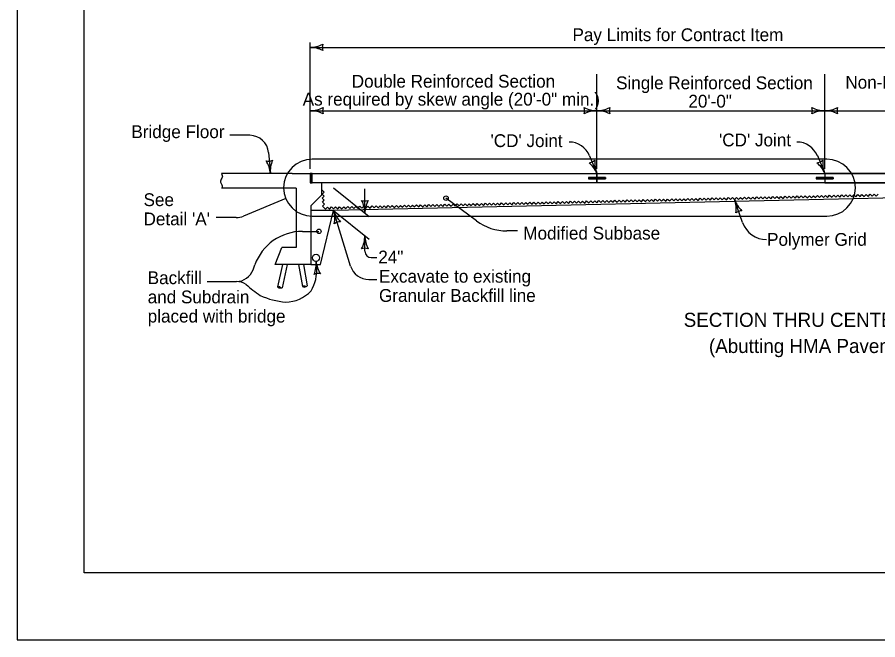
# Model space of a CAD drawing. Extents: x 10130 to 81668, y 5440 to 21644.
# Drawn here: x 13699 to 15045, y 5440 to 6413 of the extents above; entities that cross this region are included whole.
import ezdxf

# ---------------------------------------------------------------- set-up
doc = ezdxf.new("R2010")
doc.units = 0
for name, color, linetype in [('Cell', 7, 'Continuous'), ('dsnShtPlotShapeBatchPrint', 7, 'Continuous'), ('dsnStdBlockModified', 7, 'Continuous'), ('dsnStdBorder', 7, 'Continuous')]:
    doc.layers.add(name, color=color, linetype=linetype)

msp = doc.modelspace()

# ---------------------------------------------------------------- linework, layer by layer
at = {"layer": 'Cell'}
msp.add_lwpolyline([(13803.2, 7554.1), (16938.2, 7554.1), (16938.2, 5544.1), (13803.2, 5544.1)], close=True, dxfattribs=at)
at = {"layer": 'dsnShtPlotShapeBatchPrint'}
msp.add_lwpolyline([(13698.7, 5439.6), (17042.7, 5439.6), (17042.7, 8023.6), (13698.7, 8023.6)], close=True, dxfattribs=at)
at = {"layer": 'dsnStdBlockModified'}
for p, q in [((14160.1, 6153.9), (14160.1, 6168.7)), ((14160.1, 6168.7), (14605.6, 6168.7)), ((14160.1, 6153.9), (14160.1, 6168.7)), ((14605.6, 6168.7), (14605.6, 6162.2)), ((14605.6, 6162.2), (14605.6, 6168.7)), ((14605.6, 6162.2), (14605.6, 6168.7)), ((14605.6, 6168.7), (14962, 6168.7)), ((14962, 6168.7), (14962, 6162.2)), ((14175.4, 6153.9), (14160.1, 6153.9)), ((14197.2, 6153.9), (14175.4, 6153.9)), ((14605.6, 6153.9), (14197.2, 6153.9)), ((14605.6, 6162.2), (14592.2, 6162.2)), ((14592.2, 6162.2), (14592.2, 6160.4)), ((14592.2, 6162.2), (14592.2, 6160.4)), ((14618.9, 6162.2), (14592.2, 6162.2)), ((14592.2, 6162.2), (14605.6, 6162.2)), ((14592.2, 6160.4), (14605.6, 6160.4)), ((14618.9, 6162.2), (14605.6, 6162.2)), ((14605.6, 6160.4), (14605.6, 6153.9)), ((14605.6, 6153.9), (14605.6, 6160.4)), ((14605.6, 6160.3), (14618.9, 6160.4)), ((14962, 6153.9), (14605.6, 6153.9)), ((14618.9, 6160.4), (14618.9, 6162.2)), ((14948.6, 6162.2), (14948.6, 6160.4)), ((14962, 6162.2), (14948.6, 6162.2)), ((14948.6, 6162.2), (14948.6, 6160.4)), ((14948.6, 6160.4), (14962, 6160.4)), ((14975.3, 6162.2), (14962, 6162.2)), ((14962, 6160.4), (14962, 6153.9)), ((14144.9, 6078.1), (14170.7, 6078.1)), ((14067.6, 6018), (14070.3, 6025.6)), ((13995.8, 5999.6), (14041.5, 5999.6))]:
    msp.add_line(p, q, dxfattribs=at)
for centre, radius, start, end in [((14096.3, 6020), 71.3, 330.5092, 2.0511), ((14168, 6115.1), 163.6, 227.1442, 236.9942), ((14127.8, 6085.7), 118.5, 245.5915, 265.546), ((14118.3, 6022.6), 55, 270.3325, 316.7198)]:
    msp.add_arc(centre, radius, start, end, dxfattribs=at)
at = {"layer": 'dsnStdBorder'}
for p, q in [((14157.1, 6176.1), (14157.1, 6373.2)), ((14157.1, 6365.7), (15318.4, 6365.7)), ((14605.6, 6176.1), (14605.6, 6323.7)), ((14962, 6176.1), (14962, 6323.7)), ((14157.1, 6266.7), (14605.6, 6266.7)), ((14605.6, 6266.7), (14962, 6266.7)), ((14962, 6266.7), (15318.4, 6266.7)), ((14062.8, 6228.3), (14031.1, 6228.3)), ((14091.9, 6201.2), (14094.8, 6168.7)), ((14594, 6196.4), (14605.6, 6168.7)), ((14950.4, 6196.5), (14962, 6168.7)), ((14965.2, 6191), (14160.1, 6191)), ((14128.9, 6168.7), (14018.3, 6168.7)), ((14128.9, 6168.7), (14157.1, 6168.7)), ((14157.1, 6168.7), (14157.1, 6153.9)), ((14160.1, 6168.7), (14157.1, 6168.7)), ((14157.1, 6165.3), (14160.1, 6168.3)), ((14157.1, 6167.4), (14158, 6168.3)), ((14160.1, 6168.3), (14157.1, 6168.3)), ((14157.1, 6163.2), (14160.1, 6166.2)), ((14160.1, 6168.7), (15318.4, 6168.7)), ((14605.6, 6153.9), (14605.6, 6168.7)), ((15318.4, 6168.7), (14962, 6168.7)), ((14962, 6168.7), (14962, 6162.2)), ((14962, 6168.7), (14962, 6153.9)), ((14157.1, 6161.1), (14160.1, 6164.1)), ((14157.1, 6159), (14160.1, 6162)), ((14157.1, 6156.9), (14160.1, 6159.9)), ((14157.1, 6154.8), (14160.1, 6157.8)), ((14157.1, 6153.9), (14160.1, 6153.9)), ((14158.3, 6153.9), (14160.1, 6155.7)), ((15318.4, 6153.9), (14160.1, 6153.9)), ((14174.9, 6153.9), (14174.9, 6134.6)), ((14592.2, 6162.2), (14618.9, 6162.2)), ((14592.2, 6160.4), (14618.9, 6160.4)), ((14592.2, 6160.4), (14618.9, 6160.4)), ((14618.9, 6162.2), (14618.9, 6160.4)), ((14948.6, 6162.2), (14975.3, 6162.2)), ((14948.6, 6160.4), (14975.3, 6160.4)), ((14962, 6162.2), (14975.3, 6162.2)), ((14975.3, 6160.4), (14962, 6160.4)), ((14962, 6160.4), (14962, 6153.9)), ((14962, 6153.9), (15318.4, 6153.9)), ((14975.3, 6162.2), (14975.3, 6160.4)), ((14975.3, 6162.2), (14975.3, 6160.4)), ((14134.8, 6145.8), (14018.3, 6145.8)), ((14134.8, 6145.8), (14134.8, 6052.9)), ((14193.7, 6146.1), (14249, 6101.1)), ((14242.5, 6106.3), (14242.5, 6144.5)), ((14118.9, 6129.4), (14052.7, 6102.1)), ((14174.9, 6134.6), (14158.1, 6117.8)), ((15318.4, 6136.2), (14193.7, 6110.8)), ((14417.3, 6094.4), (14369.4, 6130)), ((14833.5, 6091.8), (14821, 6127.7)), ((14158.1, 6117.8), (14158.1, 6026.1)), ((14041.4, 6099.8), (14009.8, 6099.8)), ((14193.7, 6110.8), (14158.1, 6110.8)), ((14160.1, 6101.9), (14965.2, 6101.9)), ((14173, 6026.1), (14193.7, 6110.8)), ((14193.7, 6110.8), (14249, 6065.8)), ((14220.2, 6023.9), (14193.7, 6110.8)), ((14481.4, 6078.8), (14464.5, 6078.8)), ((14242.5, 6047), (14242.5, 6071)), ((14102.2, 6026.1), (14112.4, 6052.9)), ((14134.8, 6052.9), (14112.4, 6052.9)), ((14252.5, 6037), (14261.1, 6037)), ((14158.1, 6026.1), (14102.2, 6026.1)), ((14113.6, 6026.1), (14106.1, 5991.3)), ((14121.2, 6026.1), (14113.4, 5989.8)), ((14138.9, 6026.1), (14145.2, 5991.8)), ((14146.4, 6026.1), (14152.5, 5993.2)), ((14158.1, 6026.1), (14173, 6026.1)), ((14248.6, 6002.9), (14261.1, 6002.9))]:
    msp.add_line(p, q, dxfattribs=at)
for points in [[(14177.9, 6115.7), (14176.2, 6117.4), (14179.3, 6120.6), (14176, 6123.7), (14179.1, 6127), (14175.9, 6130.1), (14179, 6133.3), (14175.7, 6136.4), (14178.8, 6139.6), (14175.6, 6142.7), (14175.7, 6142.9)], [(14540.4, 6122.9), (14542, 6121.4), (14545.1, 6124.6), (14548.4, 6121.5), (14551.5, 6124.8), (14554.7, 6121.7), (14557.8, 6124.9), (14561, 6121.8), (14564.1, 6125.1), (14567.4, 6122), (14570.5, 6125.2), (14573.7, 6122.1), (14576.8, 6125.4), (14580, 6122.3), (14583.1, 6125.5), (14586.4, 6122.4), (14589.5, 6125.6), (14592.7, 6122.6), (14595.8, 6125.8), (14599, 6122.7), (14602.1, 6125.9), (14605.4, 6122.9), (14608.5, 6126.1), (14611.7, 6123), (14614.8, 6126.2), (14616.4, 6124.7)], [(14616.4, 6124.7), (14618, 6123.2), (14621.1, 6126.4), (14624.4, 6123.3), (14627.5, 6126.6), (14630.7, 6123.5), (14633.8, 6126.7), (14637, 6123.6), (14640.1, 6126.9), (14643.4, 6123.8), (14646.5, 6127), (14649.7, 6123.9), (14652.8, 6127.2), (14656.1, 6124.1), (14659.1, 6127.3), (14662.4, 6124.2), (14665.5, 6127.5), (14668.7, 6124.4), (14671.8, 6127.6), (14675.1, 6124.5), (14678.1, 6127.8), (14681.4, 6124.7), (14684.5, 6127.9), (14687.7, 6124.8), (14690.8, 6128), (14692.4, 6126.5)], [(14692.4, 6126.5), (14694.1, 6125), (14697.2, 6128.2), (14700.4, 6125.1), (14703.5, 6128.4), (14706.7, 6125.3), (14709.8, 6128.5), (14713.1, 6125.4), (14716.1, 6128.7), (14719.4, 6125.6), (14722.5, 6128.8), (14725.7, 6125.7), (14728.8, 6128.9), (14732.1, 6125.9), (14735.2, 6129.1), (14738.4, 6126), (14741.5, 6129.2), (14744.7, 6126.2), (14747.8, 6129.4), (14751.1, 6126.3), (14754.2, 6129.5), (14757.4, 6126.5), (14760.5, 6129.7), (14763.7, 6126.6), (14766.8, 6129.8), (14768.4, 6128.3)], [(14768.5, 6128.3), (14770.1, 6126.7), (14773.2, 6130), (14776.4, 6126.9), (14779.5, 6130.1), (14782.7, 6127), (14785.8, 6130.3), (14789.1, 6127.2), (14792.2, 6130.4), (14795.4, 6127.3), (14798.5, 6130.6), (14801.7, 6127.5), (14804.8, 6130.7), (14808.1, 6127.6), (14811.2, 6130.9), (14814.4, 6127.8), (14817.5, 6131), (14820.7, 6127.9), (14823.8, 6131.1), (14827.1, 6128.1), (14830.2, 6131.3), (14833.4, 6128.2), (14836.5, 6131.4), (14839.7, 6128.4), (14842.8, 6131.6), (14844.5, 6130)], [(14844.5, 6130), (14846.1, 6128.5), (14849.2, 6131.7), (14852.4, 6128.6), (14855.5, 6131.9), (14858.7, 6128.8), (14861.8, 6132), (14865.1, 6128.9), (14868.2, 6132.2), (14871.4, 6129.1), (14874.5, 6132.3), (14877.7, 6129.2), (14880.8, 6132.5), (14884.1, 6129.4), (14887.2, 6132.6), (14890.4, 6129.5), (14893.5, 6132.8), (14896.8, 6129.7), (14899.8, 6132.9), (14903.1, 6129.8), (14906.2, 6133.1), (14909.4, 6130), (14912.5, 6133.2), (14915.8, 6130.1), (14918.9, 6133.4), (14920.5, 6131.8)], [(14920.5, 6131.8), (14922.1, 6130.3), (14925.2, 6133.5), (14928.4, 6130.4), (14931.5, 6133.6), (14934.8, 6130.6), (14937.9, 6133.8), (14941.1, 6130.7), (14944.2, 6133.9), (14947.4, 6130.8), (14950.5, 6134.1), (14953.8, 6131), (14956.9, 6134.2), (14960.1, 6131.1), (14963.2, 6134.4), (14966.4, 6131.3), (14969.5, 6134.5), (14972.8, 6131.4), (14975.9, 6134.7), (14979.1, 6131.6), (14982.2, 6134.8), (14985.4, 6131.7), (14988.5, 6135), (14991.8, 6131.9), (14994.9, 6135.1), (14996.5, 6133.6)], [(14996.5, 6133.6), (14998.1, 6132.1), (15001.2, 6135.3), (15004.4, 6132.2), (15007.5, 6135.4), (15010.8, 6132.3), (15013.9, 6135.6), (15017.1, 6132.5), (15020.2, 6135.7), (15023.4, 6132.6), (15026.5, 6135.9), (15029.8, 6132.8), (15032.9, 6136), (15036.1, 6132.9), (15039.2, 6136.2), (15042.4, 6133.1), (15045.5, 6136.3)], [(14177.7, 6115.9), (14177.7, 6115.9), (14181, 6112.8), (14184.1, 6116.1), (14187.3, 6113), (14190.4, 6116.2), (14193.7, 6113.1), (14196.7, 6116.4), (14200, 6113.3), (14203.1, 6116.5), (14206.3, 6113.4), (14209.4, 6116.7), (14212.7, 6113.6), (14215.7, 6116.8), (14219, 6113.7), (14222.1, 6117), (14225.3, 6113.9), (14228.4, 6117.1), (14231.7, 6114), (14234.8, 6117.3), (14236.4, 6115.7)], [(14236.4, 6115.8), (14238, 6114.3), (14241.1, 6117.5), (14244.3, 6114.4), (14247.4, 6117.6), (14250.7, 6114.5), (14253.8, 6117.8), (14257, 6114.7), (14260.1, 6117.9), (14263.3, 6114.8), (14266.4, 6118.1), (14269.7, 6115), (14272.8, 6118.2), (14276, 6115.1), (14279.1, 6118.4), (14282.3, 6115.3), (14285.4, 6118.5), (14288.7, 6115.4), (14291.8, 6118.7), (14295, 6115.6), (14298.1, 6118.8), (14301.3, 6115.7), (14304.4, 6119), (14307.7, 6115.9), (14310.8, 6119.1), (14312.4, 6117.6)], [(14312.4, 6117.6), (14314, 6116), (14317.1, 6119.3), (14320.3, 6116.2), (14323.4, 6119.4), (14326.7, 6116.3), (14329.8, 6119.6), (14333, 6116.5), (14336.1, 6119.7), (14339.3, 6116.6), (14342.4, 6119.9), (14345.7, 6116.8), (14348.8, 6120), (14352, 6116.9), (14355.1, 6120.2), (14358.3, 6117.1), (14361.4, 6120.3), (14364.7, 6117.2), (14367.8, 6120.5), (14371, 6117.4), (14374.1, 6120.6), (14377.3, 6117.5), (14380.4, 6120.8), (14383.7, 6117.7), (14386.8, 6120.9), (14388.4, 6119.4)], [(14388.4, 6119.4), (14390, 6117.8), (14393.1, 6121.1), (14396.3, 6118), (14399.4, 6121.2), (14402.7, 6118.1), (14405.8, 6121.4), (14409, 6118.3), (14412.1, 6121.5), (14415.4, 6118.4), (14418.4, 6121.7), (14421.7, 6118.6), (14424.8, 6121.8), (14428, 6118.7), (14431.1, 6122), (14434.4, 6118.9), (14437.4, 6122.1), (14440.7, 6119), (14443.8, 6122.3), (14447, 6119.2), (14450.1, 6122.4), (14453.4, 6119.3), (14456.4, 6122.6), (14459.7, 6119.5), (14462.8, 6122.7), (14464.4, 6121.2)], [(14464.4, 6121.2), (14466, 6119.6), (14469.1, 6122.9), (14472.4, 6119.8), (14475.4, 6123), (14478.7, 6119.9), (14481.8, 6123.1), (14485, 6120.1), (14488.1, 6123.3), (14491.4, 6120.2), (14494.5, 6123.4), (14497.7, 6120.4), (14500.8, 6123.6), (14504, 6120.5), (14507.1, 6123.7), (14510.4, 6120.6), (14513.5, 6123.9), (14516.7, 6120.8), (14519.8, 6124), (14523, 6120.9), (14526.1, 6124.2), (14529.4, 6121.1), (14532.5, 6124.3), (14535.7, 6121.2), (14538.8, 6124.5), (14540.4, 6122.9)]]:
    msp.add_lwpolyline(points, dxfattribs=at)
for centre, radius in [((14369.4, 6130), 3.47), ((14170.7, 6078.1), 3.47), ((14166.1, 6036.8), 5.57)]:
    msp.add_circle(centre, radius, dxfattribs=at)
for centre, radius, start, end in [((14156.5, 6408.5), 42.7, 270, 298.0725), ((14192.4, 6365.7), 16.5, 162.2666, 197.7334), ((14156.5, 6323), 42.7, 61.9275, 90), ((14157.1, 6309.5), 42.7, 270, 298.0725), ((14157.1, 6224), 42.7, 61.9275, 90), ((14193, 6266.7), 16.5, 162.2666, 197.7334), ((14569.7, 6266.7), 16.5, 342.2666, 17.7333), ((14605.6, 6309.5), 42.7, 241.9275, 270), ((14605.6, 6224), 42.7, 90, 118.0725), ((14605.6, 6309.5), 42.7, 270, 298.0725), ((14605.6, 6224), 42.7, 61.9275, 90), ((14641.4, 6266.7), 16.5, 162.2666, 197.7334), ((14926.1, 6266.7), 16.5, 342.2666, 17.7333), ((14962, 6309.5), 42.7, 241.9275, 270), ((14962, 6224), 42.7, 90, 118.0725), ((14962, 6309.5), 42.7, 270, 298.0725), ((14962, 6224), 42.7, 61.9275, 90), ((14997.8, 6266.7), 16.5, 162.2666, 197.7334), ((14062.3, 6198.6), 29.7, 4.9696, 89.1065), ((14562.1, 6183.1), 34.7, 22.5907, 90), ((14918.4, 6183.1), 34.7, 22.5907, 90), ((14091.7, 6204.4), 16.5, 257.2356, 292.7023), ((14052.2, 6165), 42.7, 4.969, 33.0415), ((14137.3, 6172.4), 42.7, 156.8965, 184.969), ((14160.1, 6146.4), 44.6, 90, 269.9998), ((14591.8, 6201.8), 16.5, 274.8595, 310.3262), ((14566.1, 6152.3), 42.7, 22.5928, 50.6653), ((14645, 6185.1), 42.7, 174.5203, 202.5928), ((14948.2, 6201.8), 16.5, 274.8572, 310.3239), ((14922.5, 6152.3), 42.7, 22.5905, 50.663), ((15001.4, 6185.1), 42.7, 174.5181, 202.5905), ((14965.2, 6146.4), 44.6, 270.0002, 90), ((14242.5, 6142.2), 16.5, 252.2666, 287.7333), ((14199.8, 6106.3), 42.7, 360, 28.0725), ((14285.3, 6106.3), 42.7, 151.9275, 180), ((14861.4, 6141.7), 42.7, 199.1779, 227.2504), ((14780.7, 6113.7), 42.7, 351.1054, 19.1779), ((14041.4, 6129.5), 29.7, 270, 292.4496), ((14234.6, 6123.3), 42.7, 196.9537, 225.0262), ((14152.8, 6098.3), 42.7, 348.8812, 16.9537), ((14234.6, 6123.3), 42.7, 196.9537, 225.0262), ((14152.8, 6098.3), 42.7, 348.8812, 16.9537), ((14832.8, 6093.8), 16.5, 91.4446, 126.9113), ((14204.2, 6076.5), 16.5, 89.2203, 124.687), ((14204.2, 6076.5), 16.5, 89.2203, 124.687), ((14464.5, 6158), 79.2, 233.4243, 270), ((14870.9, 6104.8), 39.6, 199.1769, 270), ((14144.9, 5998.9), 79.2, 90, 160.3012), ((14199.8, 6071), 42.7, 331.9275, 360), ((14285.3, 6071), 42.7, 180, 208.0725), ((14242.5, 6035.2), 16.5, 72.2666, 107.7334), ((14252.5, 6047), 10, 180, 270), ((14124, 6027.4), 42.5, 337.1139, 5.1864), ((14208.6, 6035.1), 42.5, 185.1864, 213.2589), ((14041.5, 6027.4), 27.7, 270, 340.3019), ((14248.6, 6032.6), 29.7, 196.9535, 270), ((14169.5, 5995.7), 16.4, 77.453, 112.9197), ((14041.5, 5971.9), 27.7, 56.8248, 90)]:
    msp.add_arc(centre, radius, start, end, dxfattribs=at)
for points in [[(14018.3, 6168.7), (14019.5, 6162.8), (14016.5, 6156.7), (14019.2, 6149.1), (14018.8, 6145.8)], [(14106.1, 5991.3), (14109.2, 5991.7), (14111, 5990), (14113.4, 5989.8)], [(14106.1, 5991.3), (14108.2, 5989.9), (14110.7, 5990)], [(14145.2, 5991.8), (14148, 5993), (14150.8, 5991.7), (14152.5, 5993.2)], [(14145.2, 5991.8), (14147.9, 5990.9), (14150, 5991.7)]]:
    msp.add_spline(points, degree=3, dxfattribs=at)

# ---------------------------------------------------------------- texts
at = {"layer": 'dsnStdBlockModified'}
for s, height, p in [('Pay Limits for Contract Item', 20, (14567.3, 6375.5)), ('Double Reinforced Section', 20, (14222, 6302.8)), ('Single Reinforced Section', 20, (14635.5, 6300.3)), ('Non-Reinforced Section', 20, (14994.2, 6301.2)), ('As required by skew angle (20\'-0" min.)', 20, (14145.3, 6274.7)), ('20\'-0"', 20, (14748.6, 6271.6)), ('Bridge Floor', 20, (13877.3, 6223.9)), ("'CD' Joint", 20, (14439.1, 6209.9)), ("'CD' Joint", 20, (14796.5, 6211)), ('See', 20, (13896.3, 6117.6)), ("Detail 'A'", 20, (13896.3, 6087.6)), ('Modified Subbase', 20, (14490.4, 6065.3)), ('Polymer Grid', 20, (14871.7, 6055.5)), ('24"', 20, (14263.5, 6028)), ('Excavate to existing', 20, (14264.6, 5997.9)), ('Backfill', 20, (13902.8, 5995.6)), ('and Subdrain', 20, (13902.8, 5965.6)), ('Granular Backfill line', 20, (14264.6, 5967.9)), ('placed with bridge', 20, (13902.8, 5935.6)), ('(Abutting HMA Pavement)', 22, (14780.8, 5887.9))]:
    msp.add_text(s, height=height, dxfattribs=at).set_placement(p)
at = {"layer": 'dsnStdBorder'}
msp.add_text('SECTION THRU CENTERLINE', height=22, dxfattribs=at).set_placement((14741.3, 5928.8))

doc.saveas('drawing.dxf')
